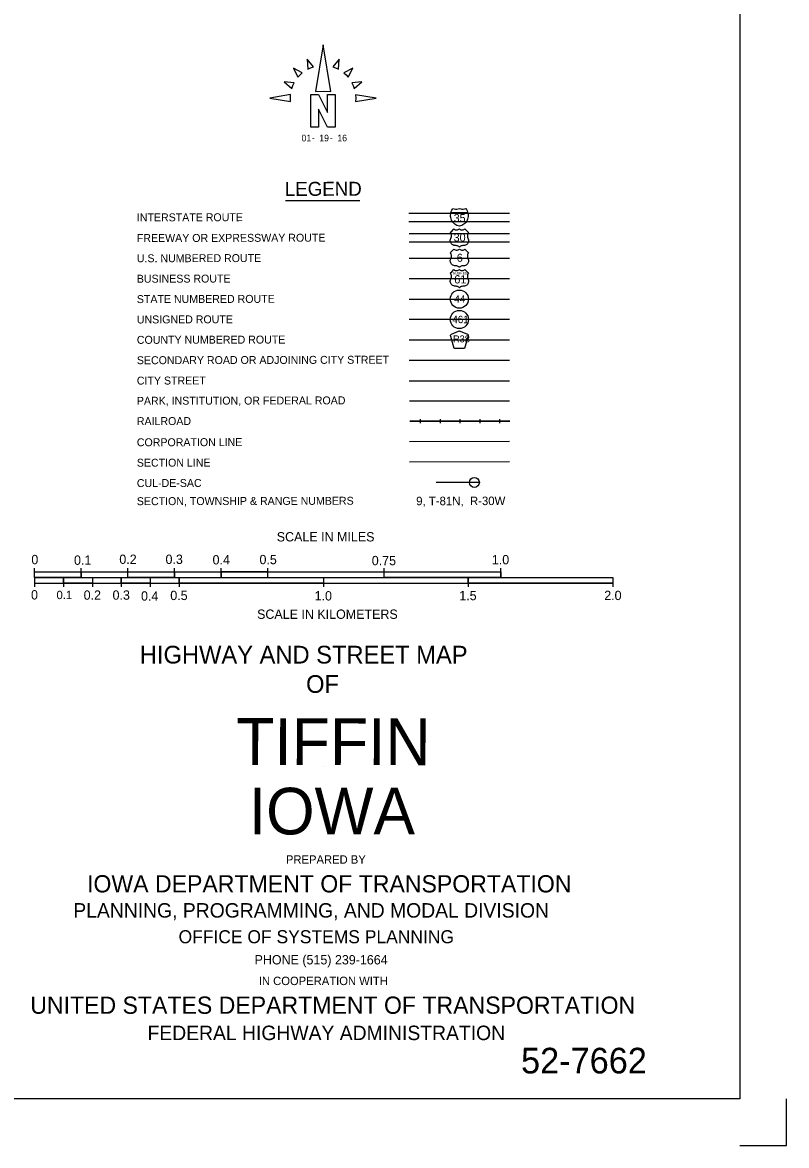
# Model space of a CAD drawing. Extents: x 281.94 to 289.14, y 116.09 to 120.89.
# Drawn here: x 287.499 to 289.138, y 116.087 to 118.495 of the extents above; entities that cross this region are included whole.
import ezdxf

# ---------------------------------------------------------------- set-up
doc = ezdxf.new("R2010")
doc.units = 0
for name, color, linetype in [('tdCiMapCityName', 7, 'Continuous'), ('tdCiMapFrame', 7, 'Continuous'), ('tdCiMapTitleBlock', 7, 'Continuous')]:
    doc.layers.add(name, color=color, linetype=linetype)

msp = doc.modelspace()

# ---------------------------------------------------------------- linework, layer by layer
at = {"layer": 'tdCiMapFrame'}
for points in [[(289.038, 120.7868), (289.038, 116.1868), (282.038, 116.1868), (282.038, 120.7868), (289.038, 120.7868)], [(289.038, 116.0868), (289.138, 116.0868), (289.138, 116.1868)]]:
    msp.add_lwpolyline(points, dxfattribs=at)
at = {"layer": 'tdCiMapTitleBlock'}
for p, q in [((288.1439, 118.4473), (288.1439, 118.4473)), ((288.0635, 118.1137), (288.2226, 118.1137)), ((288.5435, 118.0857), (288.328, 118.0857)), ((288.328, 118.0687), (288.5435, 118.0687)), ((288.4181, 118.0873), (288.4545, 118.0873)), ((288.3282, 118.0426), (288.5435, 118.0426)), ((288.5435, 118.0244), (288.3282, 118.0244)), ((288.3282, 117.9895), (288.5435, 117.9895)), ((288.5436, 117.9457), (288.3283, 117.9457)), ((288.3284, 117.902), (288.5436, 117.902)), ((288.5437, 117.8583), (288.3285, 117.8583)), ((288.3286, 117.8146), (288.5437, 117.8146)), ((288.3286, 117.7709), (288.5437, 117.7709)), ((288.3288, 117.7271), (288.5438, 117.7271)), ((288.5439, 117.5964), (288.3291, 117.596)), ((288.5439, 117.5527), (288.3291, 117.5523)), ((288.4791, 117.5088), (288.3861, 117.5087)), ((287.5251, 117.3169), (287.5251, 117.3249)), ((287.6251, 117.3169), (287.6251, 117.3249)), ((287.7251, 117.3169), (287.7251, 117.3249)), ((287.8251, 117.3169), (287.8251, 117.3249)), ((287.9251, 117.3169), (287.9251, 117.3249)), ((288.0251, 117.3169), (288.0251, 117.3249)), ((288.2751, 117.3169), (288.2751, 117.3249)), ((288.5251, 117.3169), (288.5251, 117.3249)), ((287.5251, 117.3049), (287.5251, 117.3169)), ((287.5251, 117.3169), (288.5251, 117.3169)), ((287.5251, 117.3049), (287.5251, 117.2929)), ((287.5251, 117.3049), (287.5871, 117.3049)), ((287.5871, 117.3049), (287.6251, 117.3049)), ((287.5871, 117.3049), (287.5871, 117.2989)), ((287.5871, 117.2989), (287.5871, 117.2929)), ((287.6251, 117.3049), (287.6251, 117.3169)), ((287.6251, 117.3049), (287.6491, 117.3049)), ((287.6491, 117.3049), (287.6491, 117.3049)), ((287.6491, 117.3049), (287.7111, 117.3049)), ((287.6491, 117.3049), (287.6491, 117.2929)), ((287.7111, 117.3049), (287.7251, 117.3049)), ((287.7111, 117.3049), (287.7111, 117.2989)), ((287.7111, 117.2989), (287.7111, 117.2929)), ((287.7251, 117.3109), (287.7251, 117.3169)), ((287.7251, 117.3049), (287.7251, 117.3109)), ((287.7251, 117.3049), (287.7251, 117.3049)), ((287.7251, 117.3049), (287.7731, 117.3049)), ((287.7731, 117.3049), (287.8251, 117.3049)), ((287.7731, 117.3049), (287.7731, 117.2929)), ((287.8251, 117.3049), (287.8251, 117.3169)), ((287.8251, 117.3049), (287.8351, 117.3049)), ((287.8351, 117.3049), (287.9251, 117.3049)), ((287.8351, 117.3049), (287.8351, 117.2989)), ((287.8351, 117.2989), (287.8351, 117.2929)), ((287.9251, 117.3109), (287.9251, 117.3169)), ((287.9251, 117.3049), (287.9251, 117.3109)), ((287.9251, 117.3049), (288.0251, 117.3049)), ((288.0251, 117.3049), (288.0251, 117.3169)), ((288.0251, 117.3049), (288.0251, 117.3049)), ((288.0251, 117.3049), (288.1451, 117.3049)), ((288.1451, 117.3049), (288.2751, 117.3049)), ((288.1451, 117.3049), (288.1451, 117.2929)), ((288.2751, 117.3109), (288.2751, 117.3169)), ((288.2751, 117.3049), (288.2751, 117.3109)), ((288.2751, 117.3049), (288.2751, 117.3049)), ((288.2751, 117.3049), (288.4551, 117.3049)), ((288.4551, 117.3049), (288.5251, 117.3049)), ((288.4551, 117.3049), (288.4551, 117.2989)), ((288.4551, 117.2989), (288.4551, 117.2929)), ((288.5251, 117.3049), (288.5251, 117.3169)), ((288.5251, 117.3049), (288.7651, 117.3049)), ((288.7651, 117.3049), (288.7651, 117.2929)), ((287.5251, 117.2929), (287.5251, 117.2849)), ((287.5251, 117.2929), (288.7651, 117.2929)), ((287.5871, 117.2929), (287.5871, 117.2849)), ((287.6491, 117.2929), (287.6491, 117.2849)), ((287.7111, 117.2929), (287.7111, 117.2849)), ((287.7731, 117.2929), (287.7731, 117.2849)), ((287.8351, 117.2929), (287.8351, 117.2849)), ((288.1451, 117.2929), (288.1451, 117.2849)), ((288.4551, 117.2929), (288.4551, 117.2849)), ((288.7651, 117.2929), (288.7651, 117.2849)), ((288.1451, 116.8993), (288.1451, 116.8993)), ((289.038, 116.1868), (289.038, 116.1868))]:
    msp.add_line(p, q, dxfattribs=at)
for points in [[(288.1606, 118.3474), (288.1439, 118.4473), (288.1277, 118.3474), (288.1439, 118.3482)], [(288.1234, 118.4003), (288.1094, 118.4165), (288.1112, 118.3951), (288.1171, 118.3979)], [(288.1768, 118.3951), (288.1784, 118.4165), (288.1645, 118.4), (288.1707, 118.3979)], [(288.0993, 118.3873), (288.0801, 118.397), (288.09, 118.3778), (288.0944, 118.3827)], [(288.198, 118.3778), (288.2076, 118.397), (288.1885, 118.3871), (288.1934, 118.3827)], [(288.082, 118.3661), (288.0606, 118.3677), (288.0771, 118.3538), (288.0792, 118.36)], [(288.2109, 118.3537), (288.2272, 118.3677), (288.2057, 118.3659), (288.2086, 118.36)], [(288.0742, 118.3407), (288.0298, 118.3332), (288.0742, 118.326), (288.0739, 118.3332)], [(288.2135, 118.3258), (288.2579, 118.3332), (288.2135, 118.3404), (288.2139, 118.3332)], [(288.4293, 118.0951), (288.4306, 118.0951), (288.4334, 118.0954), (288.4363, 118.0961), (288.439, 118.0955), (288.4417, 118.0951), (288.4445, 118.0951), (288.4472, 118.0954), (288.4501, 118.0961), (288.4517, 118.0939), (288.453, 118.0914), (288.454, 118.0888), (288.4545, 118.0873), (288.455, 118.0846), (288.4552, 118.0818), (288.4551, 118.079), (288.4547, 118.0763), (288.4539, 118.0737), (288.4529, 118.0711), (288.4515, 118.0687), (288.4499, 118.0664), (288.448, 118.0644), (288.4459, 118.0626), (288.4436, 118.0611), (288.4412, 118.0598), (288.4386, 118.0588), (288.4363, 118.0582), (288.4336, 118.0589), (288.431, 118.06), (288.4286, 118.0613), (288.4263, 118.0629), (288.4243, 118.0647), (288.4224, 118.0668), (288.4208, 118.069), (288.4195, 118.0715), (288.4185, 118.074), (288.4178, 118.0767), (288.4174, 118.0794), (288.4174, 118.0822), (288.4176, 118.085), (288.4181, 118.0873), (288.4189, 118.0899), (288.42, 118.0924), (288.4215, 118.0948), (288.4224, 118.0961), (288.4251, 118.0955), (288.4279, 118.0951)], [(288.4181, 118.0873), (288.4189, 118.0899), (288.42, 118.0924), (288.4215, 118.0948), (288.4224, 118.0961), (288.4251, 118.0955), (288.4279, 118.0951), (288.4306, 118.0951), (288.4334, 118.0954), (288.4363, 118.0961), (288.439, 118.0955), (288.4417, 118.0951), (288.4445, 118.0951), (288.4472, 118.0954), (288.4501, 118.0961), (288.4517, 118.0939), (288.453, 118.0914), (288.454, 118.0888), (288.4545, 118.0873)], [(288.4363, 118.0582), (288.4336, 118.0589), (288.431, 118.06), (288.4286, 118.0613), (288.4263, 118.0629), (288.4243, 118.0647), (288.4224, 118.0668), (288.4208, 118.069), (288.4195, 118.0715), (288.4185, 118.074), (288.4178, 118.0767), (288.4174, 118.0794), (288.4174, 118.0822), (288.4176, 118.085), (288.4181, 118.0873), (288.4545, 118.0873), (288.455, 118.0846), (288.4552, 118.0818), (288.4551, 118.079), (288.4547, 118.0763), (288.4539, 118.0737), (288.4529, 118.0711), (288.4515, 118.0687), (288.4499, 118.0664), (288.448, 118.0644), (288.4459, 118.0626), (288.4436, 118.0611), (288.4412, 118.0598), (288.4386, 118.0588)], [(288.4206, 118.0486), (288.4245, 118.0525), (288.4258, 118.0515), (288.4273, 118.0508), (288.429, 118.0504), (288.4306, 118.0503), (288.4323, 118.0505), (288.4339, 118.051), (288.4353, 118.0518), (288.4363, 118.0525), (288.4376, 118.0515), (288.4392, 118.0508), (288.4408, 118.0504), (288.4425, 118.0503), (288.4441, 118.0505), (288.4457, 118.051), (288.4471, 118.0518), (288.4481, 118.0525), (288.4558, 118.0447), (288.4548, 118.0433), (288.454, 118.0416), (288.4535, 118.0399), (288.4533, 118.0381), (288.4534, 118.0363), (288.4538, 118.0345), (288.4544, 118.0329), (288.4553, 118.031), (288.4557, 118.0292), (288.4558, 118.0274), (288.4557, 118.0256), (288.4552, 118.0239), (288.4544, 118.0222), (288.4534, 118.0207), (288.4522, 118.0194), (288.4507, 118.0183), (288.4491, 118.0175), (288.4474, 118.017), (288.4456, 118.0168), (288.4434, 118.0167), (288.4417, 118.0166), (288.4401, 118.0161), (288.4386, 118.0154), (288.4373, 118.0144), (288.4363, 118.0134), (288.4351, 118.0146), (288.4338, 118.0155), (288.4323, 118.0162), (288.4306, 118.0166), (288.4292, 118.0167), (288.4275, 118.0167), (288.4257, 118.0169), (288.424, 118.0173), (288.4223, 118.0181), (288.4208, 118.0191), (288.4195, 118.0203), (288.4184, 118.0218), (288.4176, 118.0234), (288.417, 118.0251), (288.4167, 118.0269), (288.4168, 118.0287), (288.4171, 118.0305), (288.4178, 118.0322), (288.4187, 118.0343), (288.4192, 118.0361), (288.4193, 118.0379), (288.4191, 118.0397), (288.4186, 118.0414), (288.4179, 118.0431), (288.4167, 118.0447)], [(288.4206, 118.0052), (288.4245, 118.009), (288.4258, 118.0081), (288.4273, 118.0074), (288.429, 118.007), (288.4306, 118.0069), (288.4323, 118.0071), (288.4339, 118.0076), (288.4353, 118.0083), (288.4363, 118.009), (288.4376, 118.0081), (288.4392, 118.0074), (288.4408, 118.007), (288.4425, 118.0069), (288.4441, 118.0071), (288.4457, 118.0076), (288.4471, 118.0083), (288.4481, 118.009), (288.4558, 118.0013), (288.4548, 117.9998), (288.454, 117.9982), (288.4535, 117.9964), (288.4533, 117.9946), (288.4534, 117.9928), (288.4538, 117.9911), (288.4544, 117.9894), (288.4553, 117.9875), (288.4557, 117.9858), (288.4558, 117.984), (288.4557, 117.9821), (288.4552, 117.9804), (288.4544, 117.9788), (288.4534, 117.9773), (288.4522, 117.976), (288.4507, 117.9749), (288.4491, 117.9741), (288.4474, 117.9735), (288.4456, 117.9733), (288.4434, 117.9733), (288.4417, 117.9731), (288.4401, 117.9727), (288.4386, 117.9719), (288.4373, 117.9709), (288.4363, 117.9699), (288.4351, 117.9711), (288.4338, 117.9721), (288.4323, 117.9728), (288.4306, 117.9732), (288.4292, 117.9733), (288.4275, 117.9733), (288.4257, 117.9734), (288.424, 117.9739), (288.4223, 117.9746), (288.4208, 117.9756), (288.4195, 117.9769), (288.4184, 117.9783), (288.4176, 117.9799), (288.417, 117.9816), (288.4167, 117.9834), (288.4168, 117.9852), (288.4171, 117.987), (288.4178, 117.9887), (288.4187, 117.9908), (288.4192, 117.9926), (288.4193, 117.9944), (288.4191, 117.9962), (288.4186, 117.9979), (288.4179, 117.9996), (288.4167, 118.0013)], [(288.4206, 117.9614), (288.4245, 117.9653), (288.4258, 117.9644), (288.4273, 117.9637), (288.429, 117.9633), (288.4306, 117.9631), (288.4323, 117.9633), (288.4339, 117.9638), (288.4353, 117.9646), (288.4363, 117.9653), (288.4376, 117.9644), (288.4392, 117.9637), (288.4408, 117.9633), (288.4425, 117.9631), (288.4441, 117.9633), (288.4457, 117.9638), (288.4471, 117.9646), (288.4481, 117.9653), (288.4558, 117.9576), (288.4548, 117.9561), (288.454, 117.9545), (288.4535, 117.9527), (288.4533, 117.9509), (288.4534, 117.9491), (288.4538, 117.9473), (288.4544, 117.9457), (288.4553, 117.9438), (288.4557, 117.942), (288.4558, 117.9402), (288.4557, 117.9384), (288.4552, 117.9367), (288.4544, 117.935), (288.4534, 117.9335), (288.4522, 117.9322), (288.4507, 117.9312), (288.4491, 117.9303), (288.4474, 117.9298), (288.4456, 117.9296), (288.4434, 117.9296), (288.4417, 117.9294), (288.4401, 117.929), (288.4386, 117.9282), (288.4373, 117.9272), (288.4363, 117.9262), (288.4351, 117.9274), (288.4338, 117.9283), (288.4323, 117.929), (288.4306, 117.9294), (288.4292, 117.9296), (288.4275, 117.9296), (288.4257, 117.9297), (288.424, 117.9302), (288.4223, 117.9309), (288.4208, 117.9319), (288.4195, 117.9331), (288.4184, 117.9346), (288.4176, 117.9362), (288.417, 117.9379), (288.4167, 117.9397), (288.4168, 117.9415), (288.4171, 117.9433), (288.4178, 117.945), (288.4187, 117.9471), (288.4192, 117.9489), (288.4193, 117.9507), (288.4191, 117.9525), (288.4186, 117.9542), (288.4179, 117.9559), (288.4167, 117.9576)], [(288.4363, 117.7958), (288.4252, 117.7958), (288.4177, 117.8219), (288.4173, 117.8231), (288.4172, 117.8237), (288.4172, 117.8244), (288.4176, 117.8253), (288.4183, 117.8261), (288.4192, 117.8267), (288.4346, 117.8334), (288.4353, 117.8336), (288.4363, 117.8337), (288.4372, 117.8336), (288.4379, 117.8334), (288.4534, 117.8267), (288.4543, 117.8261), (288.4549, 117.8253), (288.4553, 117.8244), (288.4553, 117.8237), (288.4553, 117.8231), (288.4473, 117.7958)], [(287.5251, 117.3169), (287.6251, 117.3169), (287.6251, 117.3049), (287.5251, 117.3049)], [(287.5871, 117.3049), (287.6491, 117.3049), (287.6491, 117.2929), (287.5871, 117.2929)], [(287.7111, 117.3049), (287.7731, 117.3049), (287.7731, 117.2929), (287.7111, 117.2929)], [(287.7251, 117.3169), (287.8251, 117.3169), (287.8251, 117.3049), (287.7251, 117.3049)], [(287.8351, 117.3049), (288.1451, 117.3049), (288.1451, 117.2929), (287.8351, 117.2929)], [(288.0251, 117.3169), (287.9251, 117.3169), (287.9251, 117.3049), (288.0251, 117.3049)], [(288.2751, 117.3169), (288.5251, 117.3169), (288.5251, 117.3049), (288.2751, 117.3049)], [(288.4551, 117.3049), (288.7651, 117.3049), (288.7651, 117.2929), (288.4551, 117.2929)]]:
    msp.add_lwpolyline(points, close=True, dxfattribs=at)
for points in [[(288.1178, 118.3406), (288.1341, 118.3406), (288.1534, 118.3021), (288.1534, 118.3076), (288.1534, 118.3406), (288.1697, 118.3406), (288.1697, 118.2704), (288.1534, 118.2704), (288.1341, 118.3091), (288.1341, 118.3015), (288.1341, 118.2704), (288.1178, 118.2704), (288.1178, 118.3406)], [(288.3292, 117.6838), (288.5438, 117.6838)], [(288.3296, 117.6405), (288.5442, 117.6405)], [(288.5442, 117.6405), (288.3296, 117.6405)], [(288.3521, 117.6447), (288.3521, 117.6405), (288.3521, 117.6362)], [(288.3947, 117.6447), (288.3947, 117.6405), (288.3947, 117.6362)], [(288.4373, 117.6447), (288.4373, 117.6405), (288.4373, 117.6362)], [(288.48, 117.6447), (288.48, 117.6405), (288.48, 117.6362)], [(288.5226, 117.6447), (288.5226, 117.6405), (288.5226, 117.6362)]]:
    msp.add_lwpolyline(points, dxfattribs=at)
for centre, radius in [((288.4363, 117.902), 0.0195), ((288.4363, 117.8583), 0.0195), ((288.4684, 117.5088), 0.0107)]:
    msp.add_circle(centre, radius, dxfattribs=at)

# ---------------------------------------------------------------- texts
at = {"layer": 'tdCiMapCityName'}
msp.add_text('TIFFIN', height=0.10026, rotation=359.8944, dxfattribs=at).set_placement((287.9574, 116.9032))
at = {"layer": 'tdCiMapTitleBlock'}
for s, height, p in [('01', 0.01403, (288.0976, 118.2404)), ('-', 0.014, (288.1197, 118.2407)), ('19', 0.01403, (288.1356, 118.2404)), ('-', 0.014, (288.1585, 118.2407)), ('16', 0.01403, (288.1744, 118.2404)), ('35', 0.01707, (288.4241, 118.0674)), ('30', 0.01735, (288.4238, 118.0254)), ('6', 0.0173, (288.4307, 117.982)), ('BUSINESS', 0.00492, (288.4226, 117.9551)), ('61', 0.01771, (288.4252, 117.9356)), ('44', 0.01592, (288.4252, 117.8941)), ('461', 0.0159, (288.421, 117.8504)), ('R38', 0.01478, (288.4225, 117.8093)), ('SCALE IN MILES', 0.02, (288.0445, 117.3823)), ('0', 0.02, (287.5181, 117.3335)), ('0.1', 0.02, (287.6096, 117.3322)), ('0.2', 0.02, (287.7068, 117.3341)), ('0.3', 0.02, (287.8059, 117.3341)), ('0.4', 0.02, (287.9068, 117.3329)), ('0.5', 0.02, (288.0075, 117.3335)), ('0.75', 0.02, (288.2483, 117.3313)), ('1.0', 0.02, (288.5059, 117.3332)), ('0', 0.02, (287.5174, 117.2579)), ('0.1', 0.018, (287.5721, 117.2586)), ('0.2', 0.02, (287.6303, 117.2573)), ('0.3', 0.02, (287.6923, 117.2573)), ('0.4', 0.02, (287.7534, 117.2554)), ('0.5', 0.02, (287.8161, 117.2566)), ('1.0', 0.02, (288.1257, 117.2557)), ('1.5', 0.02, (288.436, 117.2563)), ('2.0', 0.02, (288.7469, 117.2566)), ('SCALE IN KILOMETERS', 0.02, (288.0023, 117.2163)), ('HIGHWAY AND STREET MAP', 0.038, (287.7508, 117.1205)), ('OF', 0.038, (288.1074, 117.0576)), ('IOWA', 0.1, (287.9845, 116.754)), ('PREPARED BY', 0.018, (288.0642, 116.6912)), ('IOWA DEPARTMENT OF TRANSPORTATION', 0.037, (287.6376, 116.6296)), ('PLANNING, PROGRAMMING, AND MODAL DIVISION', 0.031, (287.6081, 116.5756)), ('OFFICE OF SYSTEMS PLANNING', 0.028, (287.8339, 116.5206)), ('PHONE (515) 239-1664', 0.02, (287.9969, 116.4752)), ('IN COOPERATION WITH', 0.018, (288.006, 116.4309)), ('UNITED STATES DEPARTMENT OF TRANSPORTATION', 0.037, (287.5158, 116.3693)), ('FEDERAL HIGHWAY ADMINISTRATION', 0.031, (287.7673, 116.3129)), ('52-7662', 0.055, (288.5685, 116.2414))]:
    msp.add_text(s, height=height, dxfattribs=at).set_placement(p)
for s, height, p in [('LEGEND', 0.03002, (288.0618, 118.1233)), ('INTERSTATE ROUTE ', 0.017012, (287.7444, 118.0687)), ('FREEWAY OR EXPRESSWAY ROUTE', 0.017012, (287.7444, 118.0244)), ('U.S. NUMBERED ROUTE', 0.017012, (287.7444, 117.981)), ('BUSINESS ROUTE', 0.017012, (287.7444, 117.9372)), ('STATE NUMBERED ROUTE', 0.017012, (287.7444, 117.8935)), ('UNSIGNED ROUTE', 0.017012, (287.7444, 117.8498)), ('COUNTY NUMBERED ROUTE', 0.017012, (287.7444, 117.8061)), ('SECONDARY ROAD OR ADJOINING CITY STREET', 0.017012, (287.7444, 117.7624)), ('CITY STREET', 0.017012, (287.7444, 117.7187)), ('PARK, INSTITUTION, OR FEDERAL ROAD', 0.017012, (287.7444, 117.6754)), ('RAILROAD', 0.01701, (287.7444, 117.6318)), ('CORPORATION LINE', 0.017012, (287.7444, 117.5864)), ('SECTION LINE', 0.017012, (287.7444, 117.5426)), ('CUL-DE-SAC', 0.01701, (287.7444, 117.4989)), ('SECTION, TOWNSHIP & RANGE NUMBERS', 0.017012, (287.7444, 117.4601)), ('9, T-81N,  R-30W', 0.018253, (288.3436, 117.4599))]:
    msp.add_text(s, height=height, rotation=0.1196, dxfattribs=at).set_placement(p)

doc.saveas('drawing.dxf')
